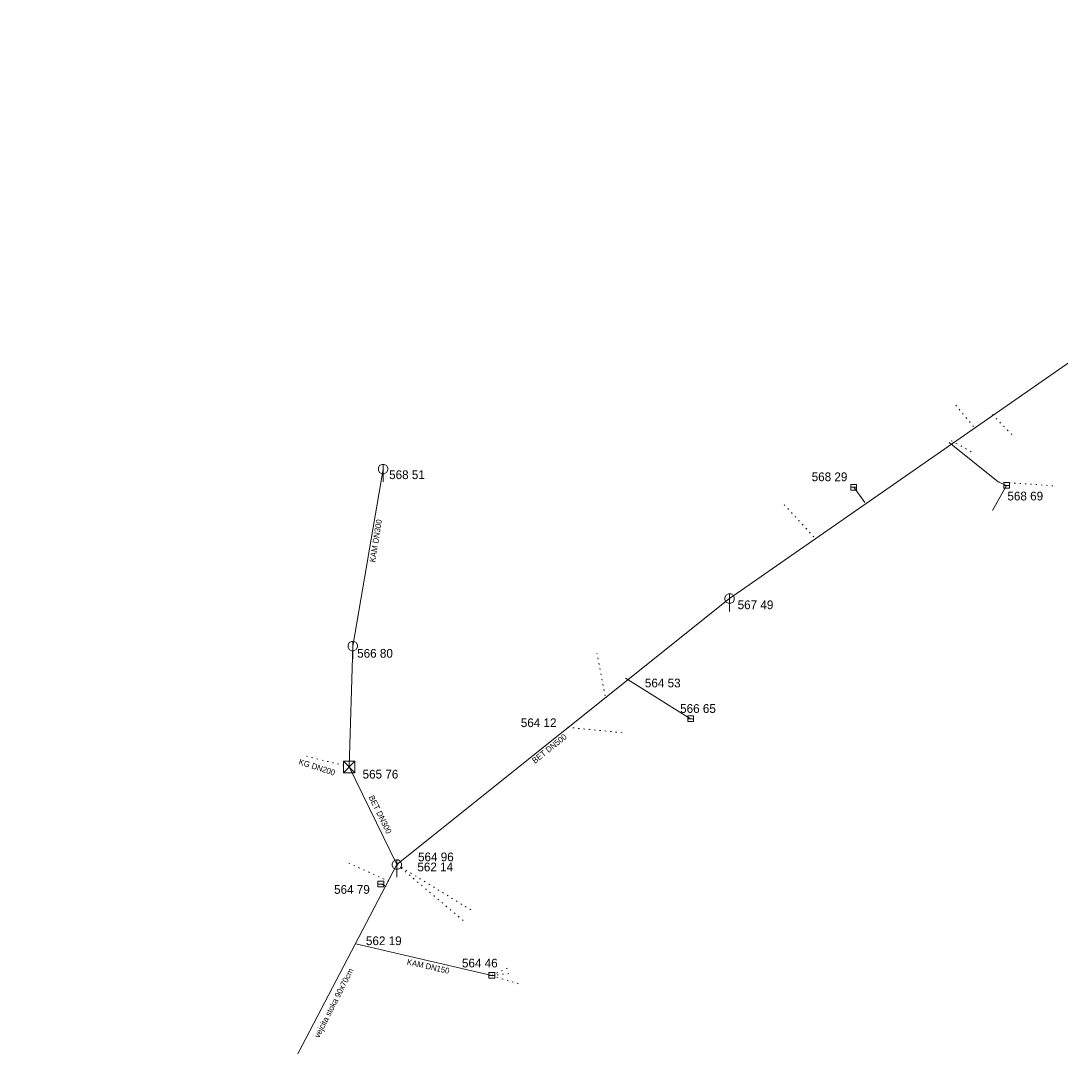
# Model space of a CAD drawing. Extents: x -710806 to -710046, y -1116920 to -1116046.
# Drawn here: x -710330.4 to -710241.1, y -1116378.5 to -1116290.4 of the extents above; entities that cross this region are included whole.
import ezdxf
from ezdxf.enums import TextEntityAlignment as Align

# ---------------------------------------------------------------- set-up
doc = ezdxf.new("R2010")
doc.units = 0
doc.header["$LTSCALE"] = 0.3
doc.linetypes.add('DOTTED', pattern=[1.5, 0.3, -1.2])
for name, color, linetype, lineweight in [('40', 7, 'Continuous', 13), ('41', 7, 'Continuous', 13), ('45', 7, 'DOTTED', 13)]:
    doc.layers.add(name, color=color, linetype=linetype, lineweight=lineweight)
doc.layers.add('43', color=7, linetype='Continuous')
doc.layers.add('44', color=7, linetype='Continuous')

msp = doc.modelspace()

# ---------------------------------------------------------------- linework, layer by layer
at = {"layer": '40'}
for points in [[(-710298.116, -1116362.85), (-710269.531, -1116340.009), (-710239.325, -1116318.997), (-710213.195, -1116302), (-710186.313, -1116290.382), (-710185.783, -1116291.255)], [(-710330.414, -1116425.31), (-710318.181, -1116401.863), (-710306.903, -1116379.643), (-710298.116, -1116362.85), (-710302.211, -1116354.462), (-710301.898, -1116344.085), (-710299.298, -1116328.891)]]:
    msp.add_lwpolyline(points, dxfattribs=at)
at = {"layer": '41'}
for p, q in [((-710299.298, -1116328.491), (-710299.298, -1116329.991)), ((-710258.623, -1116330.197), (-710259.123, -1116330.197)), ((-710259.123, -1116330.197), (-710259.123, -1116330.697)), ((-710258.623, -1116330.697), (-710258.623, -1116330.197)), ((-710245.496, -1116330.036), (-710245.996, -1116330.036)), ((-710245.996, -1116330.036), (-710245.996, -1116330.536)), ((-710245.496, -1116330.286), (-710245.996, -1116330.286)), ((-710245.496, -1116330.536), (-710245.496, -1116330.036)), ((-710258.623, -1116330.447), (-710259.123, -1116330.447)), ((-710259.123, -1116330.697), (-710258.623, -1116330.697)), ((-710245.996, -1116330.536), (-710245.496, -1116330.536)), ((-710269.531, -1116339.609), (-710269.531, -1116341.109)), ((-710301.898, -1116343.685), (-710301.898, -1116345.185)), ((-710272.631, -1116350.073), (-710273.131, -1116350.073)), ((-710273.131, -1116350.073), (-710273.131, -1116350.573)), ((-710272.631, -1116350.323), (-710273.131, -1116350.323)), ((-710273.131, -1116350.573), (-710272.631, -1116350.573)), ((-710272.631, -1116350.573), (-710272.631, -1116350.073)), ((-710302.711, -1116353.962), (-710301.711, -1116354.962)), ((-710301.711, -1116353.962), (-710302.711, -1116354.962)), ((-710298.116, -1116362.45), (-710298.116, -1116363.95)), ((-710299.243, -1116364.277), (-710299.743, -1116364.277)), ((-710299.743, -1116364.277), (-710299.743, -1116364.777)), ((-710299.243, -1116364.527), (-710299.743, -1116364.527)), ((-710299.743, -1116364.777), (-710299.243, -1116364.777)), ((-710299.243, -1116364.777), (-710299.243, -1116364.277)), ((-710289.712, -1116372.125), (-710290.212, -1116372.125)), ((-710290.212, -1116372.125), (-710290.212, -1116372.625)), ((-710289.712, -1116372.625), (-710289.712, -1116372.125)), ((-710289.712, -1116372.375), (-710290.212, -1116372.375)), ((-710290.212, -1116372.625), (-710289.712, -1116372.625))]:
    msp.add_line(p, q, dxfattribs=at)
for points in [[(-710299.698, -1116328.991), (-710299.698, -1116328.791), (-710299.598, -1116328.591), (-710299.398, -1116328.491), (-710299.198, -1116328.491), (-710298.998, -1116328.591), (-710298.898, -1116328.791), (-710298.898, -1116328.991), (-710298.998, -1116329.191), (-710299.198, -1116329.291), (-710299.398, -1116329.291), (-710299.598, -1116329.191)], [(-710269.931, -1116340.109), (-710269.931, -1116339.909), (-710269.831, -1116339.709), (-710269.631, -1116339.609), (-710269.431, -1116339.609), (-710269.231, -1116339.709), (-710269.131, -1116339.909), (-710269.131, -1116340.109), (-710269.231, -1116340.309), (-710269.431, -1116340.409), (-710269.631, -1116340.409), (-710269.831, -1116340.309)], [(-710302.298, -1116344.185), (-710302.298, -1116343.985), (-710302.198, -1116343.785), (-710301.998, -1116343.685), (-710301.798, -1116343.685), (-710301.598, -1116343.785), (-710301.498, -1116343.985), (-710301.498, -1116344.185), (-710301.598, -1116344.385), (-710301.798, -1116344.485), (-710301.998, -1116344.485), (-710302.198, -1116344.385)], [(-710302.711, -1116353.962), (-710301.711, -1116353.962), (-710301.711, -1116354.962), (-710302.711, -1116354.962)], [(-710298.516, -1116362.95), (-710298.516, -1116362.75), (-710298.416, -1116362.55), (-710298.216, -1116362.45), (-710298.016, -1116362.45), (-710297.816, -1116362.55), (-710297.716, -1116362.75), (-710297.716, -1116362.95), (-710297.816, -1116363.15), (-710298.016, -1116363.25), (-710298.216, -1116363.25), (-710298.416, -1116363.15)]]:
    msp.add_lwpolyline(points, close=True, dxfattribs=at)
at = {"layer": '45'}
for p, q in [((-710248.58, -1116325.241), (-710250.2, -1116323.298)), ((-710246.967, -1116324.204), (-710245.184, -1116326.04)), ((-710250.495, -1116326.452), (-710248.484, -1116327.563)), ((-710246.458, -1116329.99), (-710241.69, -1116330.325)), ((-710262.291, -1116334.718), (-710264.842, -1116331.952)), ((-710280.233, -1116348.37), (-710280.93, -1116344.718)), ((-710283.445, -1116351.066), (-710278.534, -1116351.55)), ((-710302.211, -1116354.462), (-710306.018, -1116353.509)), ((-710298.795, -1116364.289), (-710302.264, -1116362.72)), ((-710298.116, -1116362.85), (-710292.275, -1116367.774)), ((-710298.116, -1116362.85), (-710291.564, -1116366.869)), ((-710289.962, -1116372.375), (-710288.444, -1116371.658)), ((-710289.962, -1116372.375), (-710288.153, -1116372.184)), ((-710289.962, -1116372.375), (-710287.45, -1116373.182))]:
    msp.add_line(p, q, dxfattribs=at)
at = {"layer": '45', "linetype": 'Continuous'}
for p, q in [((-710257.927, -1116331.755), (-710258.873, -1116330.447)), ((-710278.467, -1116346.858), (-710272.881, -1116350.323)), ((-710299.493, -1116364.527), (-710299.019, -1116364.701)), ((-710289.962, -1116372.375), (-710301.63, -1116369.663))]:
    msp.add_line(p, q, dxfattribs=at)
msp.add_lwpolyline([(-710250.675, -1116326.594), (-710246.458, -1116329.99), (-710245.746, -1116330.286), (-710246.942, -1116332.432)], dxfattribs=at)

# ---------------------------------------------------------------- texts
at = {"layer": '43'}
for s, p in [('568 51 ', (-710297.1042, -1116329.746)), ('568 29 ', (-710260.8132, -1116329.926)), ('568 69 ', (-710244.0022, -1116331.578)), ('567 49 ', (-710267.1712, -1116340.918)), ('566 80 ', (-710299.8512, -1116345.085)), ('564 53 ', (-710275.1372, -1116347.635)), ('566 65 ', (-710272.1112, -1116349.826)), ('564 12 ', (-710285.7972, -1116351.048)), ('565 76 ', (-710299.3842, -1116355.466)), ('564 96 ', (-710294.6242, -1116362.572)), ('564 79 ', (-710301.8332, -1116365.366)), ('562 19 ', (-710299.0972, -1116369.773)), ('564 46 ', (-710290.8492, -1116371.688))]:
    msp.add_text(s, height=0.75, dxfattribs=at).set_placement(p, align=Align.CENTER)
msp.add_text('562 14', height=0.75, dxfattribs=at).set_placement((-710296.352, -1116363.435))
at = {"layer": '44'}
for s, rotation, p in [('KAM DN300', 81, (-710299.971, -1116336.921)), ('BET DN500', 38.7, (-710286.25, -1116354.207)), ('KG DN200', 342, (-710306.589, -1116354.227)), ('BET DN300', 296.1, (-710300.554, -1116357.061)), ('KAM DN150', 347.4, (-710297.287, -1116371.433)), ('vejcita stoka 90x70cm', 63, (-710304.797, -1116377.784))]:
    msp.add_text(s, height=0.5, rotation=rotation, dxfattribs=at).set_placement(p)

doc.saveas('drawing.dxf')
